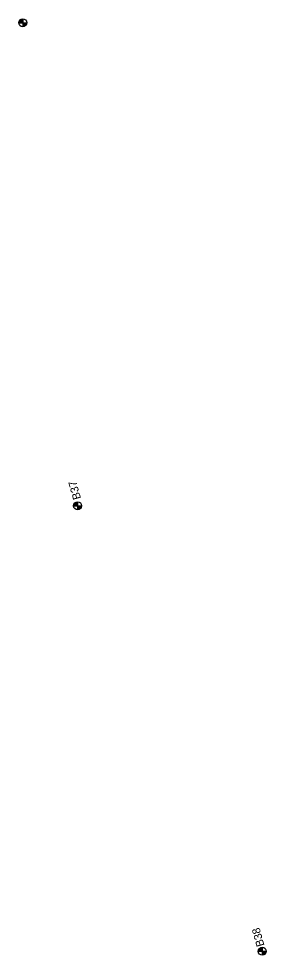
# Model space of a CAD drawing. Extents: x 345549 to 379569, y 127949 to 230467.
# Drawn here: x 360865 to 361174, y 149239 to 150410 of the extents above; entities that cross this region are included whole.
import ezdxf

# ---------------------------------------------------------------- set-up
doc = ezdxf.new("R2010")
doc.units = 0
for name, color, linetype in [('E_SOIL_BORE1 [KAPUR_CADDS_LEVELS]', 7, 'Continuous'), ('E_SOIL_BORE2 [KAPUR_CADDS_LEVELS]', 7, 'Continuous'), ('P_MARK', 7, 'Continuous')]:
    doc.layers.add(name, color=color, linetype=linetype)

msp = doc.modelspace()

# ---------------------------------------------------------------- linework, layer by layer
at = {"layer": 'P_MARK'}
for p, q in [((360870, 150410), (360870, 150400)), ((360865, 150405), (360875, 150405)), ((360933.5, 149801.2), (360943.5, 149801.2)), ((360938.5, 149806.2), (360938.5, 149796.2)), ((361169.4, 149249.4), (361169.4, 149239.4)), ((361164.4, 149244.4), (361174.4, 149244.4))]:
    msp.add_line(p, q, dxfattribs=at)
for centre in [(360870, 150405), (360938.5, 149801.2), (361169.4, 149244.4)]:
    msp.add_circle(centre, 5, dxfattribs=at)
for centre, radius, start, end in [((360870, 150405), 4.5, 89.9869, 179.9869), ((360870, 150405), 4, 89.9869, 179.9869), ((360870, 150405), 3.5, 89.9869, 179.9869), ((360870, 150405), 3, 89.9869, 179.9869), ((360870, 150405), 2.5, 89.9869, 179.9869), ((360870, 150405), 2, 89.9869, 179.9869), ((360870, 150405), 1.5, 89.9869, 179.9869), ((360870, 150405), 1, 89.9869, 179.9869), ((360870, 150405), 0.5, 89.9869, 179.9869), ((360870, 150405), 4.5, 269.9869, 359.9869), ((360870, 150405), 4, 269.9869, 359.9869), ((360870, 150405), 3.5, 269.9869, 359.9869), ((360870, 150405), 3, 269.9869, 359.9869), ((360870, 150405), 2.5, 269.9869, 359.9869), ((360870, 150405), 2, 269.9869, 359.9869), ((360870, 150405), 1.5, 269.9869, 359.9869), ((360870, 150405), 1, 269.9869, 359.9869), ((360870, 150405), 0.5, 269.9869, 359.9869), ((360938.5, 149801.2), 4.5, 89.9869, 179.9869), ((360938.5, 149801.2), 4, 89.9869, 179.9869), ((360938.5, 149801.2), 3.5, 89.9869, 179.9869), ((360938.5, 149801.2), 3, 89.9869, 179.9869), ((360938.5, 149801.2), 2.5, 89.9869, 179.9869), ((360938.5, 149801.2), 2, 89.9869, 179.9869), ((360938.5, 149801.2), 1.5, 89.9869, 179.9869), ((360938.5, 149801.2), 1, 89.9869, 179.9869), ((360938.5, 149801.2), 0.5, 89.9869, 179.9869), ((360938.5, 149801.2), 4.5, 269.9869, 359.9869), ((360938.5, 149801.2), 4, 269.9869, 359.9869), ((360938.5, 149801.2), 3.5, 269.9869, 359.9869), ((360938.5, 149801.2), 3, 269.9869, 359.9869), ((360938.5, 149801.2), 2.5, 269.9869, 359.9869), ((360938.5, 149801.2), 2, 269.9869, 359.9869), ((360938.5, 149801.2), 1.5, 269.9869, 359.9869), ((360938.5, 149801.2), 1, 269.9869, 359.9869), ((360938.5, 149801.2), 0.5, 269.9869, 359.9869), ((361169.4, 149244.4), 4.5, 89.9869, 179.9869), ((361169.4, 149244.4), 4, 89.9869, 179.9869), ((361169.4, 149244.4), 3.5, 89.9869, 179.9869), ((361169.4, 149244.4), 3, 89.9869, 179.9869), ((361169.4, 149244.4), 2.5, 89.9869, 179.9869), ((361169.4, 149244.4), 2, 89.9869, 179.9869), ((361169.4, 149244.4), 1.5, 89.9869, 179.9869), ((361169.4, 149244.4), 1, 89.9869, 179.9869), ((361169.4, 149244.4), 0.5, 89.9869, 179.9869), ((361169.4, 149244.4), 4.5, 269.9869, 359.9869), ((361169.4, 149244.4), 4, 269.9869, 359.9869), ((361169.4, 149244.4), 3.5, 269.9869, 359.9869), ((361169.4, 149244.4), 3, 269.9869, 359.9869), ((361169.4, 149244.4), 2.5, 269.9869, 359.9869), ((361169.4, 149244.4), 2, 269.9869, 359.9869), ((361169.4, 149244.4), 1.5, 269.9869, 359.9869), ((361169.4, 149244.4), 1, 269.9869, 359.9869), ((361169.4, 149244.4), 0.5, 269.9869, 359.9869)]:
    msp.add_arc(centre, radius, start, end, dxfattribs=at)

# ---------------------------------------------------------------- texts
at = {"layer": 'E_SOIL_BORE1 [KAPUR_CADDS_LEVELS]'}
msp.add_text('B37', height=10, rotation=105.7466, dxfattribs=at).set_placement((360942.9, 149810.5))
at = {"layer": 'E_SOIL_BORE2 [KAPUR_CADDS_LEVELS]'}
msp.add_text('B38', height=10, rotation=105.7466, dxfattribs=at).set_placement((361172.2, 149251.8))

doc.saveas('drawing.dxf')
